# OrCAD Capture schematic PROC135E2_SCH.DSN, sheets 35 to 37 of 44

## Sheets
35 35. USB0 TYPE-C DRP & TEST LED: size C; title: USB0 TYPE-C DRP & USER TEST LED
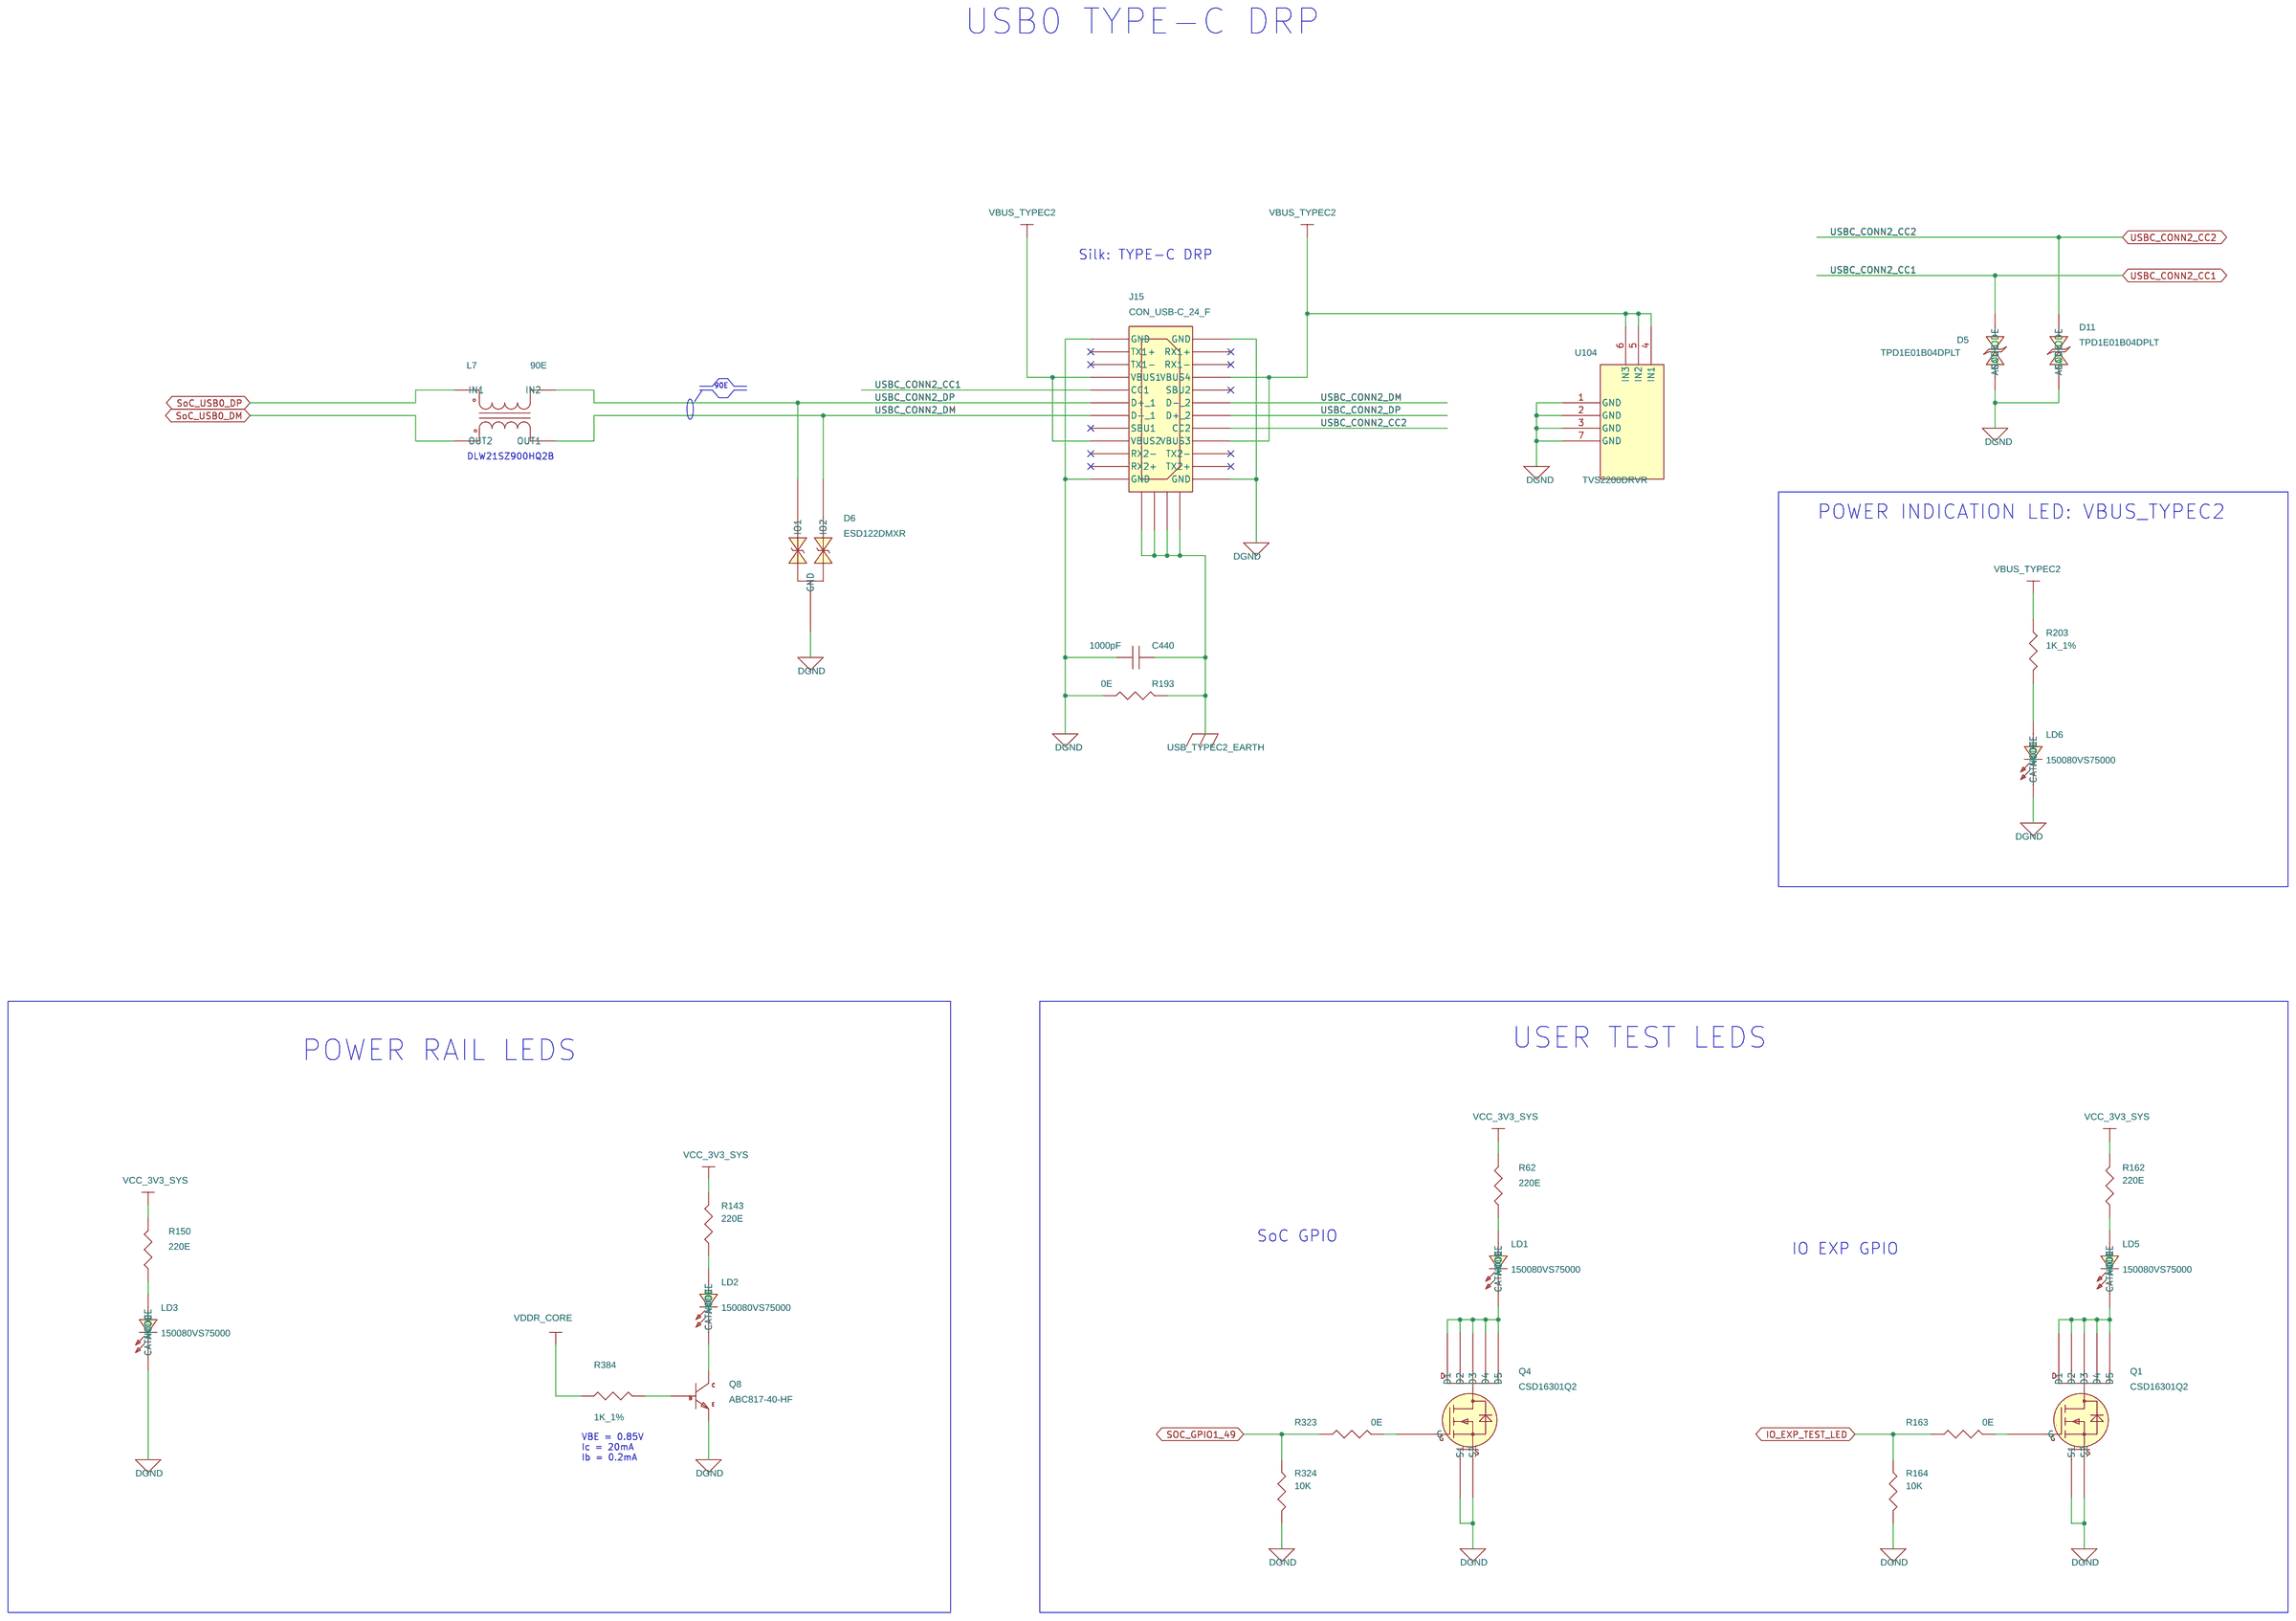
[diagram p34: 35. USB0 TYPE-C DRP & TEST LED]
36 36. SoC UART1 FET SWITCH & BUFF: size C; title: SoC UART1 FET SWITCH & BUFFER
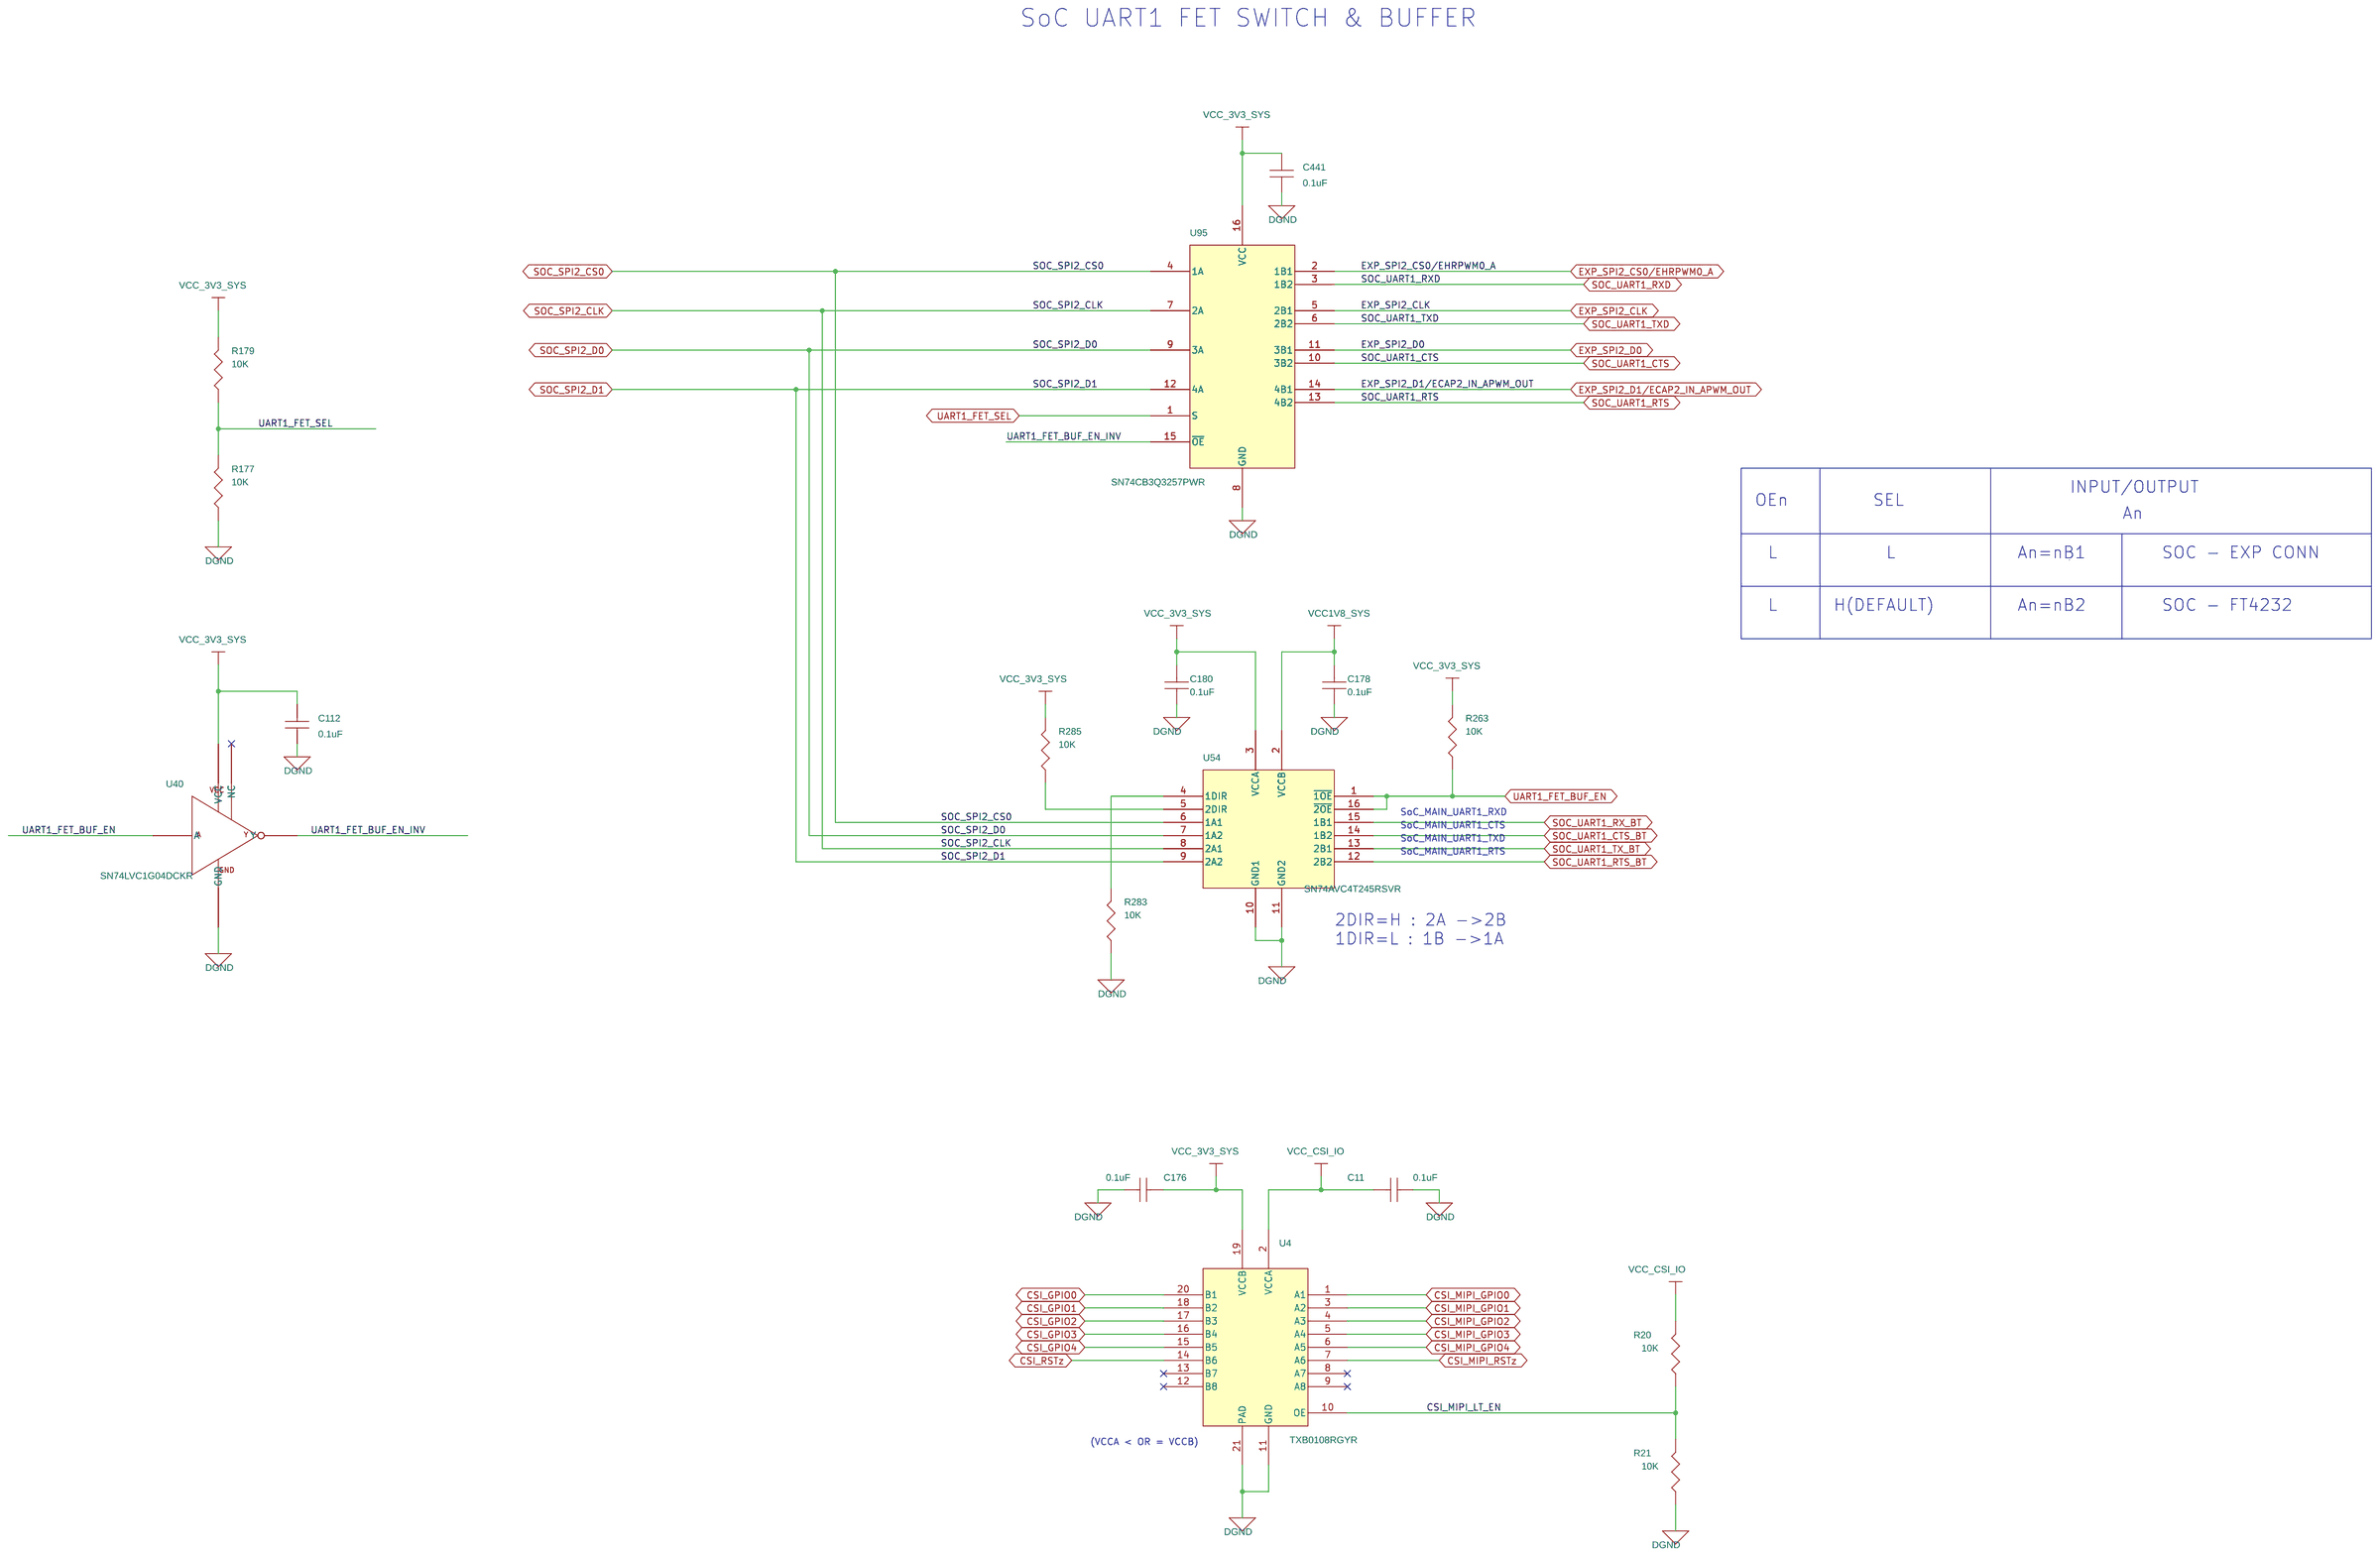
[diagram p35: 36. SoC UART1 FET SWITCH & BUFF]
37 37. CSI INTERFACE: size C; title: CSI INTERFACE
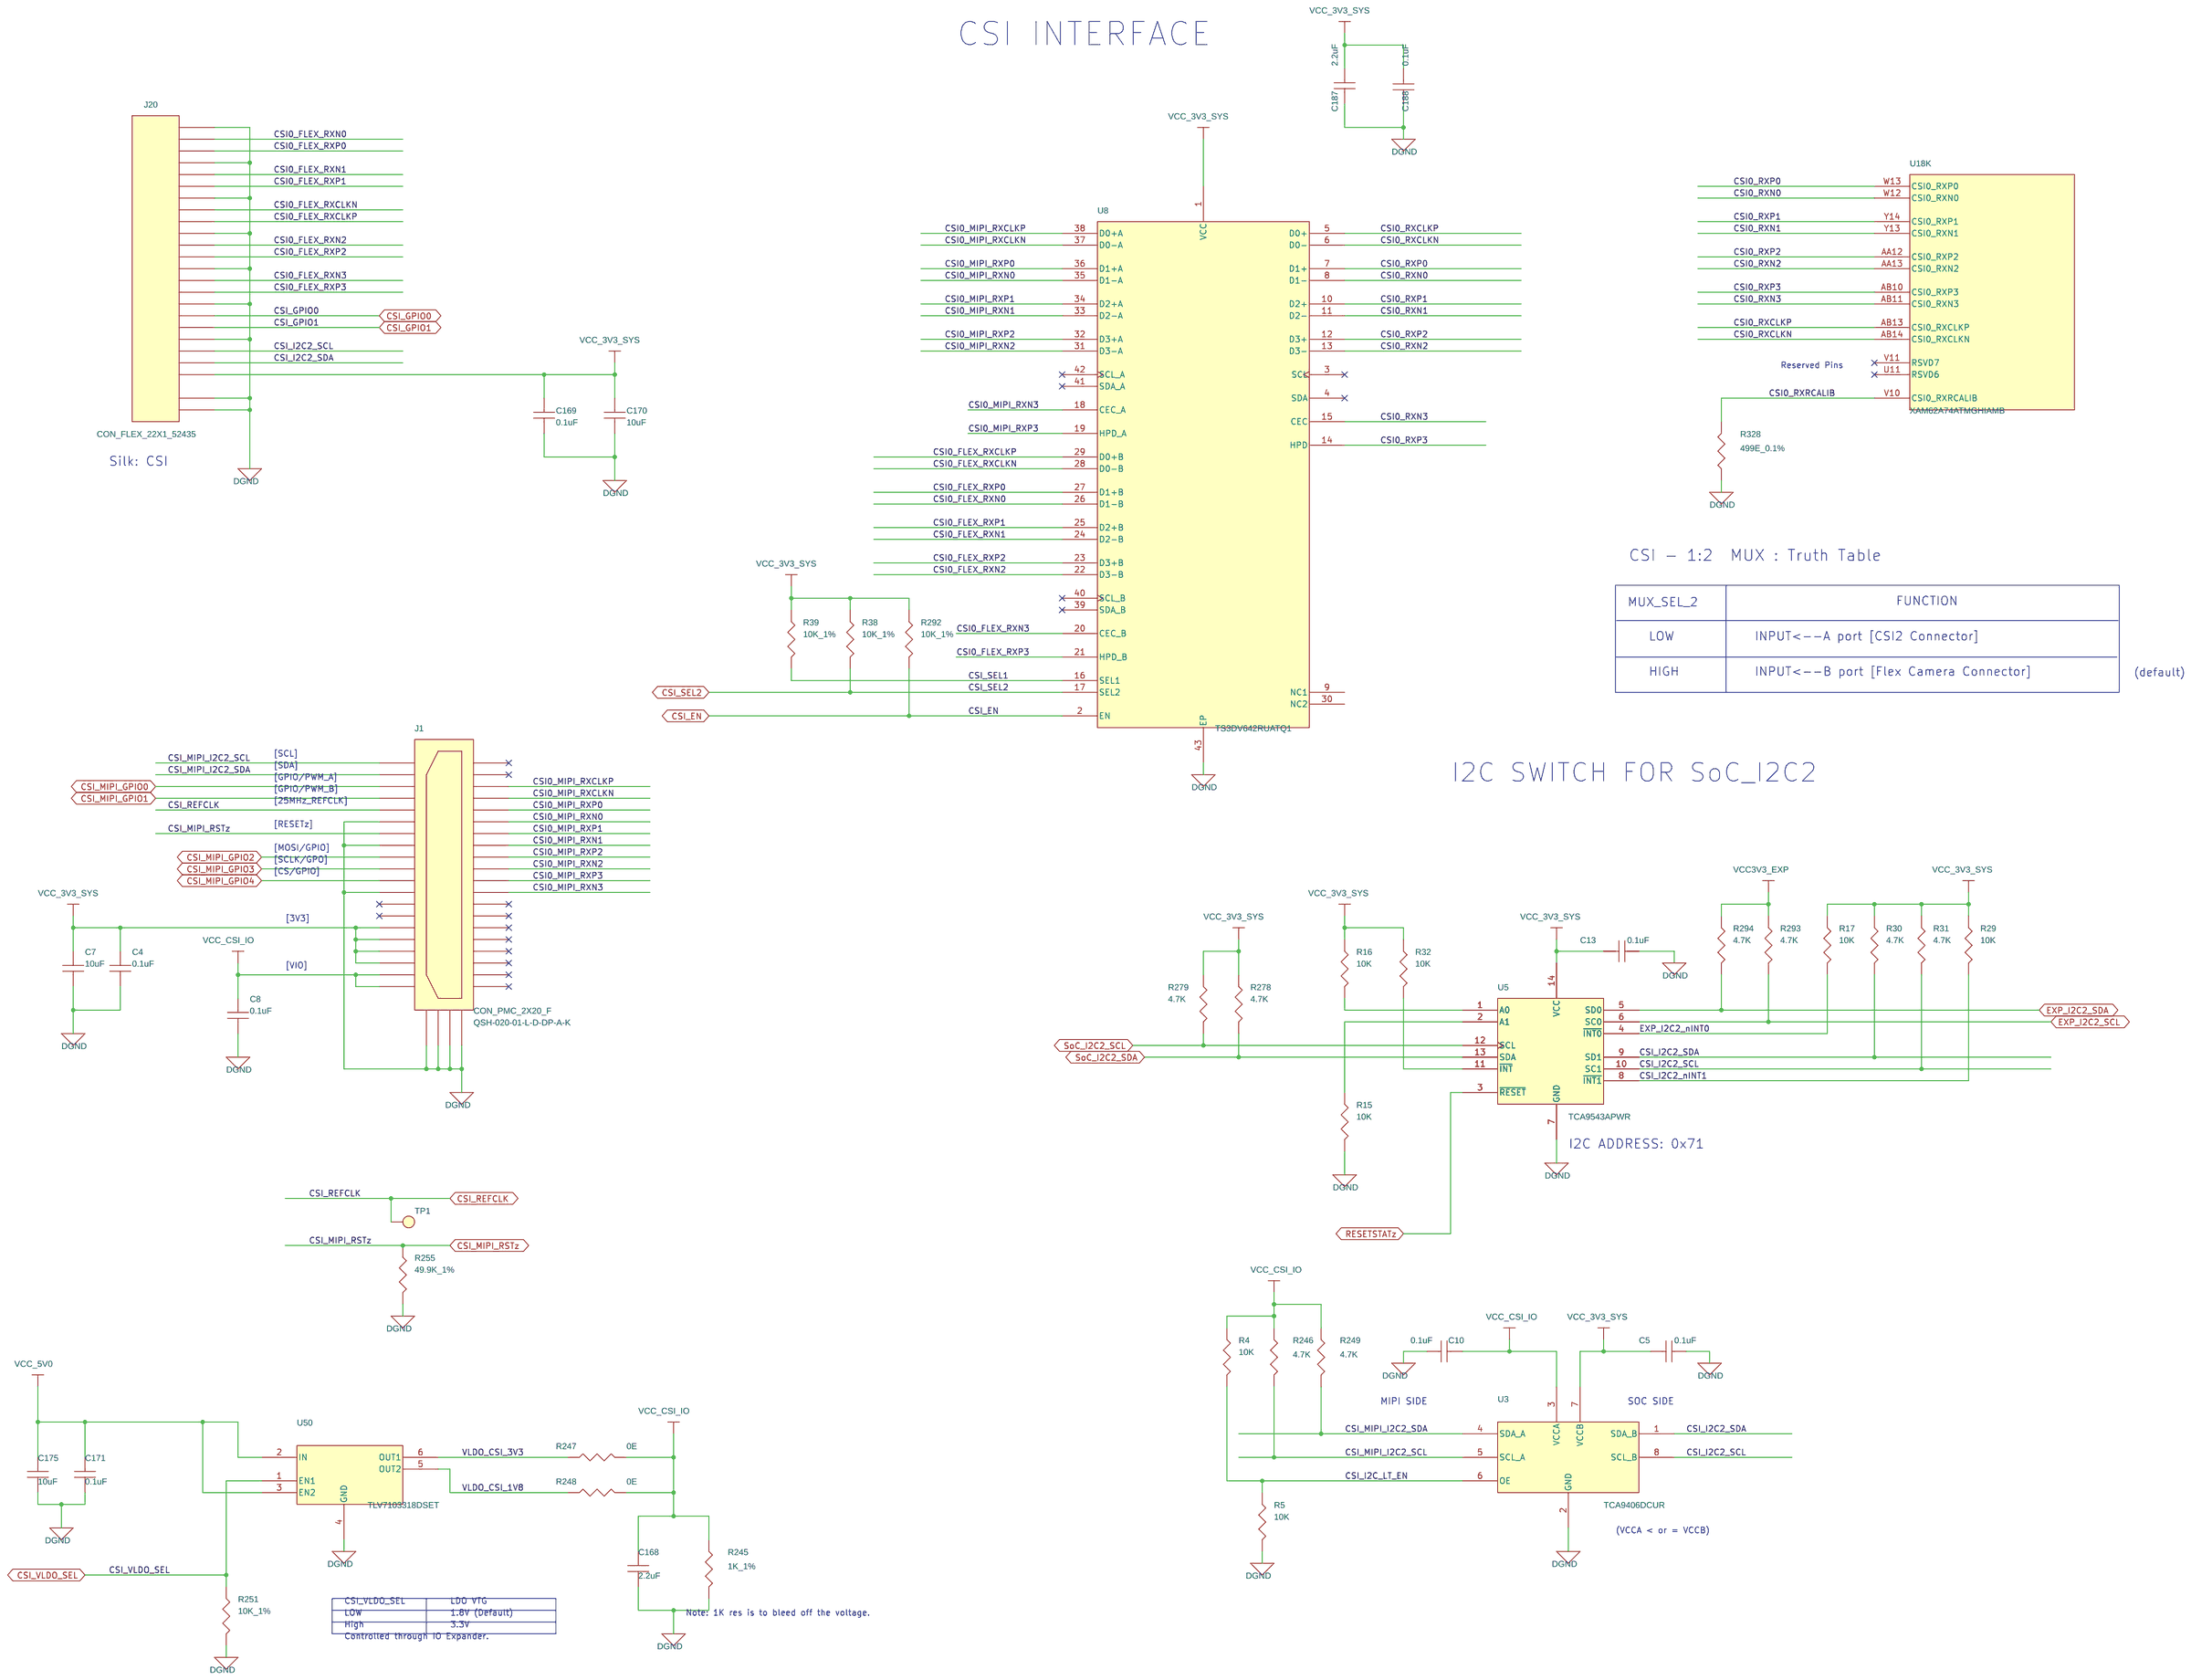
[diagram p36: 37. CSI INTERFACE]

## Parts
sheet 31. SOC WKUP & GPMC
U18  XAM62A74ATMGHIAMB  [FBGA484_31-49_710X710_2-7]  (sections A,B,C,D,E,F,G,H,I,J,K,L,M,N,O,P,Q)
sheet 35. USB0 TYPE-C DRP & TEST LED
C440  1000pF  [CAP1206_1-75]
D5  TPD1E01B04DPLT  [DIO_DFN0201_0-4]
D6  ESD122DMXR  [X2SON3_ESD122DMX_30X40_0-4]
D11  TPD1E01B04DPLT  [DIO_DFN0201_0-4]
J15  CON_USB-C_24_F  [CON_USBC24_2012670_S_R_S_3-9]
L7  90E  [IND4_DLW21H_90X60_SMD_1-4]
LD1  150080VS75000  [LED_150080VS75000_80X50_SMD_0-8]
LD2  150080VS75000  [LED_150080VS75000_80X50_SMD_0-8]
LD3  150080VS75000  [LED_150080VS75000_80X50_SMD_0-8]
LD5  150080VS75000  [LED_150080VS75000_80X50_SMD_0-8]
LD6  150080VS75000  [LED_150080VS75000_80X50_SMD_0-8]
Q1  CSD16301Q2  [WSON6_CSD13202Q2_80X80_0-8]
Q4  CSD16301Q2  [WSON6_CSD13202Q2_80X80_0-8]
Q8  ABC817-40-HF  [SOT23-123_1-2]
R62  220E  [RES0402_0-5]
R143  220E  [RES0402_0-5]
R150  220E  [RES0402_0-5]
R162  220E  [RES0402_0-5]
R163  0E  [RES0402_0-5]
R164  10K  [RES0201_0-5]
R193  0E  [RES0603_0-75]
R203  1K_1%  [RES0402_0-5]
R323  0E  [RES0402_0-5]
R324  10K  [RES0201_0-5]
R384  1K_1%  [RES0402_0-5]
U104  TVS2200DRVR  [SON6_25-59_85X85_0-8]
sheet 36. SoC UART1 FET SWITCH & BUFF
C11  0.1uF  [CAP0402_0-75]
C112  0.1uF  [CAP0201_0-5]
C176  0.1uF  [CAP0402_0-75]
C178  0.1uF  [CAP0201_0-5]
C180  0.1uF  [CAP0201_0-5]
C441  0.1uF  [CAP0402_0-75]
R20  10K  [RES0201_0-5]
R21  10K  [RES0201_0-5]
R177  10K  [RES0201_0-5]
R179  10K  [RES0201_0-5]
R263  10K  [RES0201_0-5]
R283  10K  [RES0201_0-5]
R285  10K  [RES0201_0-5]
U4  TXB0108RGYR  [QFN20_19-68_185X145_1]
U40  SN74LVC1G04DCKR  [SC70-5]
U54  SN74AVC4T245RSVR  [UQFN16_TMUX1574_70X100_0-6]
U95  SN74CB3Q3257PWR  [TSSOP16_25-59_205X180]
sheet 37. CSI INTERFACE
C4  0.1uF  [CAP0402_0-75]
C5  0.1uF  [CAP0402_0-75]
C7  10uF  [CAP0402_0-75]
C8  0.1uF  [CAP0402_0-75]
C10  0.1uF  [CAP0402_0-75]
C13  0.1uF  [CAP0402_0-75]
C168  2.2uF  [CAP0402_0-75]
C169  0.1uF  [CAP0402_0-75]
C170  10uF  [CAP0402_0-75]
C171  0.1uF  [CAP0402_0-75]
C175  10uF  [CAP0805_1-5]
C187  2.2uF  [CAP0402_0-75]
C188  0.1uF  [CAP0201_0-5]
J1  CON_PMC_2X20_F  [CON_PMC2X20_QSH-020-01-D-DP-A_S_S_S_3-4]
J20  CON_FLEX_22X1_52435  [CON_FLEX22X1_52435_S_R_S]
R4  10K  [RES0201_0-5]
R5  10K  [RES0201_0-5]
R15  10K  [RES0201_0-5]
R16  10K  [RES0201_0-5]
R17  10K  [RES0201_0-5]
R29  10K  [RES0201_0-5]
R30  4.7K  [RES0201_0-5]
R31  4.7K  [RES0201_0-5]
R32  10K  [RES0201_0-5]
R38  10K_1%  [RES0402_0-5]
R39  10K_1%  [RES0402_0-5]
R245  1K_1%  [RES0402_0-5]
R246  4.7K  [RES0201_0-5]
R247  0E  [RES0402_0-5]
R248  0E  [RES0402_0-5]
R249  4.7K  [RES0201_0-5]
R251  10K_1%  [RES0402_0-5]
R255  49.9K_1%  [RES0402_0-5]
R278  4.7K  [RES0201_0-5]
R279  4.7K  [RES0201_0-5]
R292  10K_1%  [RES0402_0-5]
R293  4.7K  [RES0201_0-5]
R294  4.7K  [RES0201_0-5]
R328  499E_0.1%  [RES0402_0-5]
TP1  TP20_SMD  [TP20_SMD]
U3  TCA9406DCUR  [VSSOP8_19-68_85X95]
U5  TCA9543APWR  [TSSOP14_25-59_205X180_1-2]
U8  TS3DV642RUATQ1  [TQFN42_19-68_140X360_0-8]
U50  TLV7103318DSET  [WSON6_19-68_60X60]

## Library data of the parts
U18 = AM62A-EVM_SOC_FCBGA484: IC AM62A SK EVM SoC MICROPROCESSOR FCBGA484; Chkd/date: PRAVEEN/190922; Crtd /date: PRAVEEN/190922; Custom_Duty: 15%; Customs_HS_Code: 85423100; Distributor_name: NA; Distributor_part_number: NA; Footprint Path: Y:\MIS_DATABASE\Library\ALTIUM_TOOL\PCB_FOOTPRINTS\Altium_Footprint_Lib.PcbLib; Height: 2.65MM; Library Ref: AM62A-EVM_SoC_FCBGA484; Mfr_name: TEXAS INSTRUMENTS; Mistral Part No: 141220090002; Package: FCBGA484; Part_type: ICS\DIGITAL\MICROPROCESSOR; Project: TI_AM62A_SK_EVM; RoHS: NA; Temperature: NA; Tolerance: NA; Voltage: NA; Wattage: NA; Weight: NA; Datasheet: Y:\MIS_DATABASE\DATASHEETS\ICS\DIGITAL\MICROCONTROLLER\AM62A_SK_EVM.PDF
C440 = CAP: CAP CERAMIC 1000pF 2KV 10% X7R 1206; Chkd/date: SHREESHAIL/291106; Crtd /date: MAZHAR/281106; Custom_Duty: 15%; Customs_HS_Code: 85322990; Distributor_name: DIGIKEY; Distributor_part_number: 478-2956-1-ND; Footprint Path: Y:\MIS_DATABASE\Library\ALTIUM_TOOL\PCB_FOOTPRINTS\Altium_Footprint_Lib.PcbLib; Height: 1.52MM; Library Path: Y:\MIS_DATABASE\Library\ALTIUM_TOOL\SCHEMATICS_PARTS\MS_DISCRETE_Library.schlib; Mfr_name: AVX CORPORATION; Mfr_part_number: 1206GC102KAT1A; Mistral Part No: 120015080006-R; Package: 1206; Part_type: CAPACITORS\CERAMIC; Project: ADR1B; RoHS: RoHS; Temperature: -55°C+125°C; Tolerance: 10%; Voltage: 2KV; Wattage: NA; Weight: 16.2mg; Datasheet: Y:\MIS_DATABASE\DATASHEETS\CAPACITORS\AVX_HV-MLC.PDF
D5 D11 = DIODE_TVS_DUAL: DIODE 1CH ESD PROTECTION FOR USB TYPE-C AND THUNDERBOLT3 X2SON2; Chkd/date: MANIRAJA/230920; Crtd /date: ALVY/230920; Custom_Duty: 15%; Customs_HS_Code: 85412900; Distributor_name: DIGIKEY; Distributor_part_number: 296-44484-1-ND; Footprint Path: Y:\MIS_DATABASE\Library\ALTIUM_TOOL\PCB_FOOTPRINTS\Altium_Footprint_Lib.PcbLib; Height: 0.32MM; Library Path: Y:\MIS_DATABASE\Library\ALTIUM_TOOL\SCHEMATICS_PARTS\MS_DISCRETE_Library.schlib; Mfr_name: TEXAS INSTRUMENTS; Mistral Part No: 130020090037-R; Package: X2SON2; Part_type: DIODE\TVS; Project: AM64X_SKEVM; RoHS: RoHS; Temperature: -40°C+125°C; Tolerance: NA; Voltage: NA; Wattage: NA; Weight: 0.2mg; Datasheet: Y:\MIS_DATABASE\DATASHEETS\DISCRETES\DIODES\TPD1E01B04.PDF
D6 = DIODE_ESD122DMXR: DIODE 2-CH ESD PROTECTION FOR USB TYPE-C AND HDMI 2.0 X2SON-3; Chkd/date: MANIRAJA/140817; Crtd /date: MANIRAJA/140817; Custom_Duty: 15%; Customs_HS_Code: 85412900; Distributor_name: DIGIKEY; Distributor_part_number: ESD122DMXR-ND; Height: 0.40MM; Mfr_name: TEXAS INSTRUMENTS; Mistral Part No: 130017080015-R; Package: X2SON-3; Part_type: DIODE\TVS; Project: TI_SVB_CONTROLLER CARD; RoHS: RoHS; Temperature: -40°C+125°C; Tolerance: NA; Voltage: NA; Wattage: NA; Weight: NA; Datasheet: Y:\MIS_DATABASE\DATASHEETS\DISCRETES\DIODES\ESD122XX.PDF
J15 = CON_USB-C_24_1240183621: CON USB-C TYPE 24POS FEMALE RT SMD; Chkd/date: MANIRAJA/050618; Crtd /date: ALVY/040618; Custom_Duty: 24%; Customs_HS_Code: 85369090; Distributor_name: DIGIKEY; Distributor_part_number: WM17992CT-ND; Footprint Path: Y:\MIS_DATABASE\Library\ALTIUM_TOOL\PCB_FOOTPRINTS\Altium_Footprint_Lib.PcbLib; Height: 3.86MM; Library Path: Y:\MIS_DATABASE\Library\ALTIUM_TOOL\SCHEMATICS_PARTS\MS_CONNECTOR_Library.schlib; Mfr_name: MOLEX; Mfr_part_number: 2012670005; Mistral Part No: 150018060002-R; Package: SMD; Part_type: CONNECTOR\USB; Project: TI_J7SVB_USB_ADD-ON-CARD; RoHS: RoHS; Temperature: -40°C+105°C; Tolerance: NA; Voltage: NA; Wattage: NA; Weight: 0.686g; Datasheet: Y:\MIS_DATABASE\DATASHEETS\CONNECTORS\2012670X.PDF
L7 = INDUCTOR_DLW31S: IND COMMON MODE CHOKE 90E 280mA SMD; Chkd/date: MANIRAJA/270619; Crtd /date: MANIRAJA/270619; Custom_Duty: 24%; Customs_HS_Code: 85437099; Distributor_name: NA; Distributor_part_number: NA; Footprint Path: Y:\MIS_DATABASE\Library\ALTIUM_TOOL\PCB_FOOTPRINTS\Altium_Footprint_Lib.PcbLib; Height: 1.40MM; Library Path: Y:\MIS_DATABASE\Library\ALTIUM_TOOL\SCHEMATICS_PARTS\MS_DISCRETE_Library.schlib; Mfr_name: MURATA; Mfr_part_number: DLW21SZ900HQ2B; Mistral Part No: 130019060035-R; Package: SMD; Part_type: INDUCTOR; Project: TI_J7ES_CP; RoHS: RoHS; Temperature: -40°C+105°C; Tolerance: NA; Voltage: NA; Wattage: NA; Weight: 11mg; Datasheet: Y:\MIS_DATABASE\DATASHEETS\DISCRETES\INDUCTORS\DLW21SZ900HQ2B.PDF
LD1-LD3 LD5 LD6 = DIODE_LED: DIODE LED BRIGHT GREEN SMD; Chkd/date: MANIRAJA/180820; Crtd /date: ALVY/180820; Custom_Duty: 24%; Customs_HS_Code: 85439000; Distributor_name: DIGIKEY; Distributor_part_number: 732-4986-1-ND; Footprint Path: Y:\MIS_DATABASE\Library\ALTIUM_TOOL\PCB_FOOTPRINTS\Altium_Footprint_Lib.PcbLib; Height: 0.80MM; Library Path: Y:\MIS_DATABASE\Library\ALTIUM_TOOL\SCHEMATICS_PARTS\MS_OPTO_Library.schlib; Mfr_name: WURTH ELECTRONICS; Mistral Part No: 130020080012-R; Package: SMD; Part_type: OPTO\LED; Project: AM64x_EVM_BRD; RoHS: RoHS; Temperature: -40°C+85°C; Tolerance: NA; Voltage: NA; Wattage: NA; Weight: 10mg; Datasheet: Y:\MIS_DATABASE\DATASHEETS\DISCRETES\LEDS\150080VS75000.PDF
Q1 Q4 = MOSFET_CSD17313Q2: IC MOSFET N-CHANNEL NEXFET 25V WSON6; Chkd/date: ALVY/071220; Crtd /date: MANIRAJA/071220; Custom_Duty: 15%; Customs_HS_Code: 85423100; Distributor_name: DIGIKEY; Distributor_part_number: 296-25260-1-ND; Footprint Path: Y:\MIS_DATABASE\Library\ALTIUM_TOOL\PCB_FOOTPRINTS\Altium_Footprint_Lib.PcbLib; Height: 0.80MM; Library Path: Y:\MIS_DATABASE\Library\ALTIUM_TOOL\SCHEMATICS_PARTS\MS_MOSFET_Library.schlib; Manufacturer: TEXAS INSTRUMENTS; Mfr_name: TEXAS INSTRUMENTS; Mistral Part No: 142020120008-R; Package: WSON6; Part_type: ICS\POWER\MOSFET; Project: TI_AM243x LP EVM; RoHS: RoHS; Temperature: -55°C+150°C; Tolerance: NA; Voltage: NA; Wattage: NA; Weight: 8.7mg; Datasheet: Y:\MIS_DATABASE\DATASHEETS\ICS\POWER\CSD16301Q2.PDF
Q8 = NPN_123_SOT23-3: TRANSISTOR 45V 500mA NPN GENERAL PURPOSE SOT23-3; Chkd/date: PRAVEEN/260822; Crtd /date: PRAVEEN/260822; Custom_Duty: 15%; Customs_HS_Code: 85423100; Distributor_name: MOUSER; Distributor_part_number: 750-ABC817-40-HF; Footprint Path: Y:\MIS_DATABASE\Library\ALTIUM_TOOL\PCB_FOOTPRINTS\Altium_Footprint_Lib.PcbLib; Height: 1.20MM; Library Path: Y:\MIS_DATABASE\Library\ALTIUM_TOOL\SCHEMATICS_PARTS\MS_MOSFET_Library.schlib; Mfr_name: COMCHIP; Mistral Part No: 142022080040-R; Package: TO-252-3; Part_type: TRANSISTOR\BJT; Project: MS_TI_TMDS64SKEVM; RoHS: RoHS; Temperature: -55°C+150°C; Tolerance: NA; Voltage: 45V; Wattage: NA; Weight: NA; Datasheet: Y:\MIS_DATABASE\DATASHEETS\DISCRETES\TRANSISTORS_FETS\ABC817-40-HF.PDF
R62 R143 R150 R162 = RESISTOR: RES 220E 1/10W 5% 0402; Chkd/date: VASANTHA/291216; Crtd /date: GEETHA/260406; Custom_Duty: 15%; Customs_HS_Code: 85332119; Distributor_name: DIGIKEY; Distributor_part_number: P220JCT-ND; Footprint Path: Y:\MIS_DATABASE\Library\ALTIUM_TOOL\PCB_FOOTPRINTS\Altium_Footprint_Lib.PcbLib; Height: 0.40MM; Library Path: Y:\MIS_DATABASE\Library\ALTIUM_TOOL\SCHEMATICS_PARTS\MS_DISCRETE_Library.schlib; Mfr_name: PANASONIC-ECG; Mfr_part_number: ERJ-2GEJ221X; Mistral Part No: 110009030506-R; Package: 0402; Part_type: RESISTORS\FIXED; Project: RED EYE; RoHS: RoHS; Temperature: -55°C+155°C; Tolerance: 5%; Voltage: NA; Wattage: 1/10W; Weight: 0.8mg; Datasheet: Y:\MIS_DATABASE\DATASHEETS\RESISTORS\PAN-ERJSER_NOV17.PDF
R163 R323 = RESISTOR: RES 0E 1/16W JUMPER 0402; Chkd/date: VASANTHA/201216; Crtd /date: MUDDU/190810; Custom_Duty: 15%; Customs_HS_Code: 85332119; Distributor_name: DIGIKEY; Distributor_part_number: 541-0.0JCT-ND; Footprint Path: Y:\MIS_DATABASE\Library\ALTIUM_TOOL\PCB_FOOTPRINTS\Altium_Footprint_Lib.PcbLib; Height: 0.40MM; Library Path: Y:\MIS_DATABASE\Library\ALTIUM_TOOL\SCHEMATICS_PARTS\MS_DISCRETE_Library.schlib; Mfr_name: VISHAY; Mfr_part_number: CRCW04020000Z0ED; Mistral Part No: 110010080019-R; Package: 0402; Part_type: RESISTORS\FIXED; Project: PB_BUGBASE; RoHS: RoHS; Temperature: -55°C+155°C; Tolerance: NA; Voltage: NA; Wattage: 1/16W; Weight: 0.65mg; Datasheet: Y:\MIS_DATABASE\DATASHEETS\RESISTORS\CRCW0603.PDF
R4 R5 R15-R17 R20 R21 R29 R32 R164 R177 R179 R263 R283 R285 R324 = RESISTOR: RES 10K 1/20W 5% 0201; Chkd/date: MANIRAJA/050517; Crtd /date: MANIRAJA/050517; Custom_Duty: 15%; Customs_HS_Code: 85332119; Distributor_name: DIGIKEY; Distributor_part_number: 311-10KNCT-ND; Footprint Path: Y:\MIS_DATABASE\Library\ALTIUM_TOOL\PCB_FOOTPRINTS\Altium_Footprint_Lib.PcbLib; Height: 0.26MM; Library Path: Y:\MIS_DATABASE\Library\ALTIUM_TOOL\SCHEMATICS_PARTS\MS_DISCRETE_Library.schlib; Mfr_name: YAGEO AMERICA; Mfr_part_number: RC0201JR-0710KL; Mistral Part No: 110010070051-R; Package: 0201; Part_type: RESISTORS\FIXED; Project: GOLDEN-I LITE; RoHS: RoHS; Temperature: -55°C+125°C; Tolerance: 5%; Voltage: NA; Wattage: 1/20W; Weight: 0.17mg; Datasheet: Y:\MIS_DATABASE\DATASHEETS\RESISTORS\RCXXXXL-SER_MAR18.PDF
R193 = RESISTOR: RES 0E 1/10W 5% 0603; Chkd/date: MANIRAJA/051217; Crtd /date: BAVISH/180211; Custom_Duty: 15%; Customs_HS_Code: 85332119; Distributor_name: DIGIKEY; Distributor_part_number: 311-0.0GRCT-ND; Footprint Path: Y:\MIS_DATABASE\Library\ALTIUM_TOOL\PCB_FOOTPRINTS\Altium_Footprint_Lib.PcbLib; Height: 0.55MM; Library Path: Y:\MIS_DATABASE\Library\ALTIUM_TOOL\SCHEMATICS_PARTS\MS_DISCRETE_Library.schlib; Manufacturer: YAGEO AMERICA; Mfr_name: PANASONIC-ECG; Mfr_part_number: RC0603JR-070RL; Mistral Part No: 110011020013-R; Package: 0603; Part_type: RESISTORS\FIXED; Project: KENNEL; RoHS: RoHS; Temperature: -55°C+155°C; Tolerance: 5%; Voltage: NA; Wattage: 1/10W; Weight: 2mg; Datasheet: Y:\MIS_DATABASE\DATASHEETS\RESISTORS\RCXXXXL-SER_MAR18.PDF
R203 R245 R384 = RESISTOR: RES 1K 1/10W 1% 0402; Chkd/date: VASANTHA/281216; Crtd /date: MAZHAR/150506; Custom_Duty: 15%; Customs_HS_Code: 85332119; Distributor_name: DIGIKEY; Distributor_part_number: P1.00KLCT-ND; Footprint Path: Y:\MIS_DATABASE\Library\ALTIUM_TOOL\PCB_FOOTPRINTS\Altium_Footprint_Lib.PcbLib; Height: 0.40MM; Library Path: Y:\MIS_DATABASE\Library\ALTIUM_TOOL\SCHEMATICS_PARTS\MS_DISCRETE_Library.schlib; Mfr_name: PANASONIC-ECG; Mfr_part_number: ERJ-2RKF1001X; Mistral Part No: 110009030411-R; Package: 0402; Part_type: RESISTORS\FIXED; Project: VOCERA; RoHS: RoHS; Temperature: -55°C+155°C; Tolerance: 1%; Voltage: NA; Wattage: 1/10W; Weight: 0.8mg; Datasheet: Y:\MIS_DATABASE\DATASHEETS\RESISTORS\PAN-ERJSER_NOV17.PDF
U104 = TVS2200_WSON6: IC 22V FLAT-CLAMP SURGE PROTECTION DEVICE WSON6; Chkd/date: MANIRAJA/011021; Crtd /date: ALVY/011021; Custom_Duty: 15%; Customs_HS_Code: 85423100; Distributor_name: DIGIKEY; Distributor_part_number: 296-52187-1-ND; Footprint Path: Y:\MIS_DATABASE\Library\ALTIUM_TOOL\PCB_FOOTPRINTS\Altium_Footprint_Lib.PcbLib; Height: 0.80MM; Library Path: Y:\MIS_DATABASE\Library\ALTIUM_TOOL\SCHEMATICS_PARTS\MS_MISCPOWER_Library.schlib; Mfr_name: TEXAS INSTRUMENTS; Mistral Part No: 142021100001-R; Package: WSON6; Part_type: ICS\POWER; Project: TI_AM62x SKEVM_BRD; RoHS: RoHS; Temperature: -40°C+125°C; Tolerance: NA; Voltage: NA; Wattage: NA; Weight: 12mg; Datasheet: Y:\MIS_DATABASE\DATASHEETS\ICS\POWER\TVS2200.PDF
C4 C5 C8 C10 C11 C13 C169 C171 C176 C441 = CAP: CAP CERAMIC 0.1uF 50V 10% X7R 0402; Alt_Mfr_name: YAGEO AMERICA; Alt_Mfr_part_number: CC0402KRX5R8BB104; Chkd/date: MANIRAJA/261020; Crtd /date: ALVY/211020; Custom_Duty: 15%; Customs_HS_Code: 85322990; Distributor_name: DIGIKEY; Distributor_part_number: 490-10700-1-ND; Footprint Path: Y:\MIS_DATABASE\Library\ALTIUM_TOOL\PCB_FOOTPRINTS\Altium_Footprint_Lib.PcbLib; Height: 0.55MM; Library Path: Y:\MIS_DATABASE\Library\ALTIUM_TOOL\SCHEMATICS_PARTS\MS_DISCRETE_Library.schlib; Mfr_name: MURATA; Mfr_part_number: GRM155R71H104KE14D; Mistral Part No: 120011100014-R; Package: 0402; Part_type: CAPACITORS\CERAMIC; Project: J7_CP; RoHS: RoHS; Temperature: -55°C+125°C; Tolerance: 10%; Voltage: 50V; Wattage: NA; Weight: 3.1mg; Datasheet: Y:\MIS_DATABASE\DATASHEETS\CAPACITORS\GRM155R71H104KE14.PDF
C112 C178 C180 C188 = CAP: CAP CERAMIC 0.1uF 16V 10% X5R 0201; Alt_Mfr_name: YAGEO AMERICA; Alt_Mfr_part_number: CC0402KRX5R8BB104; Chkd/date: MANIRAJA/230118; Crtd /date: MANIRAJA/230118; Custom_Duty: 15%; Customs_HS_Code: 85322990; Distributor_name: DIGIKEY; Distributor_part_number: 490-14305-1-ND; Footprint Path: Y:\MIS_DATABASE\Library\ALTIUM_TOOL\PCB_FOOTPRINTS\Altium_Footprint_Lib.PcbLib; Height: 0.33MM; Library Path: Y:\MIS_DATABASE\Library\ALTIUM_TOOL\SCHEMATICS_PARTS\MS_DISCRETE_Library.schlib; Mfr_name: MURATA; Mfr_part_number: GRM033R61C104KE14D; Mistral Part No: 120009030072-R; Package: 0201; Part_type: CAPACITORS\CERAMIC; Project: TI_MAXIE_CPB; RoHS: RoHS; Temperature: -55°C+85°C; Tolerance: 10%; Voltage: 16V; Wattage: NA; Weight: 0.33mg; Datasheet: Y:\MIS_DATABASE\DATASHEETS\CAPACITORS\GRM033R61C104KE14.PDF
U4 = TXB0108RGYR_VQFN20: IC 8-BIT TRANSLATOR 15KV ESD VQFN20; Chkd/date: VASANTHA/221216; Crtd /date: MUDDU/190510; Custom_Duty: 15%; Customs_HS_Code: 85423100; Distributor_name: DIGIKEY; Distributor_part_number: 296-21528-1-ND; Height: 1.00MM; Mfr_name: TEXAS INSTRUMENTS; Mistral Part No: 141010050005-R; Package: VQFN20; Part_type: ICS\INTERFACE; Project: SHIVA; RoHS: Sb/ Br FREE; Temperature: -40°C+85°C; Tolerance: NA; Voltage: NA; Wattage: NA; Weight: 43mg; Datasheet: Y:\MIS_DATABASE\DATASHEETS\ICS\INTERFACE\TXB0108RGYR.PDF
U40 = SN74LVC1G04DCKR_SC70-5: IC SINGLE INVERTER GATE SC70-5; Chkd/date: SUHAS/221010; Crtd /date: USMAN/150709; Custom_Duty: 15%; Customs_HS_Code: 85423100; Distributor_name: DIGIKEY; Distributor_part_number: 296-11600-1-ND; Height: 1.10MM; Mfr_name: TEXAS INSTRUMENTS; Mistral Part No: 141009070007-R; Part_type: ICS\DIGITAL\GATES; Project: BUG_BASE-II; RoHS: Sb/ Br FREE; Temperature: -40°C+85°C; Datasheet: Y:\MIS_DATABASE\DATASHEETS\ICS\DIGITAL\GATES\SN74LVC1G04-1.PDF
U54 = SN74AVC4T245RSV_UQFN16: IC 2-BIT BUS TRANSCEIVER WITH CONFIGURABLE VOLTAGE TRANSLATION AND 3 STATE O/P UQFN16; Chkd/date: MANIRAJA/040520; Crtd /date: BAVISH/190411; Custom_Duty: 15%; Customs_HS_Code: 85423100; Distributor_name: DIGIKEY; Distributor_part_number: 296-24366-1-ND; Footprint Path: Y:\MIS_DATABASE\Library\ALTIUM_TOOL\PCB_FOOTPRINTS\Altium_Footprint_Lib.PcbLib; Height: 0.55MM; Library Path: Y:\MIS_DATABASE\Library\ALTIUM_TOOL\SCHEMATICS_PARTS\MS_BUSDRIVERTRANSCEIVER_Library.schlib; Mfr_name: TEXAS INSTRUMENTS; Mistral Part No: 141011040011-R; Package: UQFN16; Part_type: ICS\DIGITAL\BUSTRANSCEIVER; Project: HMC; RoHS: RoHS; Temperature: -40°C+85°C; Tolerance: NA; Voltage: NA; Wattage: NA; Weight: 41mg; Datasheet: Y:\MIS_DATABASE\DATASHEETS\ICS\DIGITAL\BUSTRANSCEIVER\SN74AVC4T245-SER.PDF
U95 = SN74CB3Q3257PWR_TSSOP16: IC 4BIT 1-OF-2 FET MULTIPLEXER/DEMULTIPLEXER TSSOP16; Chkd/date: SUHAS/251010; Crtd /date: USMAN/060109; Custom_Duty: 15%; Customs_HS_Code: 85423100; Distributor_name: DIGIKEY; Distributor_part_number: 296-19138-1-ND; Height: 1.20MM; Mfr_name: TEXAS INSTRUMENTS; Mistral Part No: 141009030117-R; Package: TSSOP16; Part_type: ICS\DIGITAL\COMBINATIONAL; Project: OMAP_EVM; RoHS: Sb/ Br FREE; Temperature: -40°C+85°C; Datasheet: Y:\MIS_DATABASE\DATASHEETS\ICS\DIGITAL\COMBINATIONAL\SN74CB3Q3257.PDF
C7 C170 = CAP: CAP CERAMIC 10uF 10V 20% X5R 0402; Chkd/date: MANIRAJA/300520; Crtd /date: ALVY/260520; Custom_Duty: 15%; Customs_HS_Code: 85322990; Distributor_name: DIGIKEY; Distributor_part_number: 490-GRM155R61A106ME11DTR-ND; Footprint Path: Y:\MIS_DATABASE\Library\ALTIUM_TOOL\PCB_FOOTPRINTS\Altium_Footprint_Lib.PcbLib; Height: 0.55MM; Library Path: Y:\MIS_DATABASE\Library\ALTIUM_TOOL\SCHEMATICS_PARTS\MS_DISCRETE_Library.schlib; Mfr_name: MURATA; Mfr_part_number: GRM155R61A106ME11D; Mistral Part No: 120013110019-R; Package: 0402; Part_type: CAPACITORS\CERAMIC; Project: QCS610_NANOSOM; RoHS: RoHS; Temperature: -55°C+85°C; Tolerance: 20%; Voltage: 10V; Wattage: NA; Weight: 3.1mg; Datasheet: Y:\MIS_DATABASE\DATASHEETS\CAPACITORS\MURATA-GXX-SER_NOV17.PDF
C168 = CAP: CAP CERAMIC 2.2uF 25V 10% X5R 0402; Chkd/date: ALVY/010721; Crtd /date: MANIRAJA/010721; Custom_Duty: 15%; Customs_HS_Code: 85322990; Distributor_name: DIGIKEY; Distributor_part_number: 490-12703-1-ND; Footprint Path: Y:\MIS_DATABASE\Library\ALTIUM_TOOL\PCB_FOOTPRINTS\Altium_Footprint_Lib.PcbLib; Height: 0.70MM; Library Path: Y:\MIS_DATABASE\Library\ALTIUM_TOOL\SCHEMATICS_PARTS\MS_DISCRETE_Library.schlib; Manufacturer: MURATA; Mfr_name: MURATA; Mfr_part_number: GRM155R61E225KE11D; Mistral Part No: 120015120001-R; Package: 0402; Part_type: CAPACITORS\CERAMIC; Project: TI_AM263X_CC; RoHS: RoHS; Temperature: -55°C+85°C; Tolerance: 10%; Voltage: 25V; Wattage: NA; Weight: 1.5mg; Datasheet: Y:\MIS_DATABASE\DATASHEETS\CAPACITORS\GRM155R61E225KE11.PDF
C175 = CAP: CAP CERAMIC 10uF 50V 10% X5R 0805; Chkd/date: MANIRAJA/010321; Crtd /date: ALVY/010321; Custom_Duty: 15%; Customs_HS_Code: 85322990; Distributor_name: DIGIKEY; Distributor_part_number: 490-18663-1-ND; Footprint Path: Y:\MIS_DATABASE\Library\ALTIUM_TOOL\PCB_FOOTPRINTS\Altium_Footprint_Lib.PcbLib; Height: 1.45MM; Library Path: Y:\MIS_DATABASE\Library\ALTIUM_TOOL\SCHEMATICS_PARTS\MS_DISCRETE_Library.schlib; Manufacturer: MURATA; Mfr_name: MURATA; Mfr_part_number: GRM21BR61H106KE43L; Mistral Part No: 120021030002-R; Package: 0805; Part_type: CAPACITORS\CERAMIC; Project: J7ES_SK_BRD; RoHS: RoHS; Temperature: -55°C+85°C; Tolerance: 10%; Voltage: 50V; Wattage: NA; Weight: 6.4mg; Datasheet: Y:\MIS_DATABASE\DATASHEETS\CAPACITORS\GRM21BR61H106KE43.PDF
C187 = CAP: CAP CERAMIC 2.2uF 25V 10% X5R 0402; Chkd/date: ALVY/010721; Crtd /date: MANIRAJA/010721; Custom_Duty: 15%; Customs_HS_Code: 85322990; Distributor_name: DIGIKEY; Distributor_part_number: 490-12703-1-ND; Footprint Path: Y:\MIS_DATABASE\Library\ALTIUM_TOOL\PCB_FOOTPRINTS\Altium_Footprint_Lib.PcbLib; Height: 0.70MM; Library Path: Y:\MIS_DATABASE\Library\ALTIUM_TOOL\SCHEMATICS_PARTS\MS_DISCRETE_Library.schlib; Mfr_name: MURATA; Mfr_part_number: GRM155R61E225KE11D; Mistral Part No: 120015120001-R; Package: 0402; Part_type: CAPACITORS\CERAMIC; Project: TI_AM263X_CC; RoHS: RoHS; Temperature: -55°C+85°C; Tolerance: 10%; Voltage: 25V; Wattage: NA; Weight: 1.5mg; Datasheet: Y:\MIS_DATABASE\DATASHEETS\CAPACITORS\GRM155R61E225KE11.PDF
J1 = CON_PMC_20X2_F_DP_TI: CON PMC 2X20 0.50MM PITCH FEMALE ST SMD; Chkd/date: MANIRAJA/251018; Crtd /date: ALVY/251018; Custom_Duty: 24%; Customs_HS_Code: 85369090; Distributor_name: DIGIKEY; Distributor_part_number: SAM10648-ND; Footprint Path: Y:\MIS_DATABASE\Library\ALTIUM_TOOL\PCB_FOOTPRINTS\Altium_Footprint_Lib.PcbLib; Height: 3.33MM; Library Path: Y:\MIS_DATABASE\Library\ALTIUM_TOOL\SCHEMATICS_PARTS\MS_CONNECTOR_Library.schlib; Library Ref: CON_PMC_20X2_F_DP; Mfr_name: SAMTEC; Mfr_part_number: QSH-020-01-L-D-DP-A-K; Mistral Part No: 150018100049-R; Package: SMD; Part_type: CONNECTOR\PMC; Project: TI_J7ES_EVM_CP; RoHS: RoHS; Temperature: -55°C+125°C; Tolerance: NA; Voltage: NA; Wattage: NA; Weight: NA; Datasheet: Y:\MIS_DATABASE\DATASHEETS\CONNECTORS\QSH-SERIES.PDF
J20 = CON_22X1_2SH: CON FPC 22X1 0.50MM PITCH TPM RT SMD; Chkd/date: PRAVEEN/090822; Crtd /date: PRAVEEN/090822; Custom_Duty: 24%; Customs_HS_Code: 85369090; Distributor_name: DIGIKEY; Distributor_part_number: WM6753CT-ND; Height: 2.00MM; Mfr_name: MOLEX; Mfr_part_number: 52435-2271; Mistral Part No: 150022080019-R; Package: SMD; Part_type: CONNECTOR\FPC; Project: JHAHP_SVB; RoHS: RoHS; Temperature: -20°C to +85°C; Tolerance: NA; Voltage: NA; Wattage: NA; Datasheet: Y:\MIS_DATABASE\DATASHEETS\CONNECTORS\52435.PDF
R30 R31 R246 R249 R278 R279 R293 R294 = RESISTOR: RES 4.7K 1/20W 5% 0201; Chkd/date: MANIRAJA/200921; Crtd /date: ALVY/200921; Custom_Duty: 15%; Customs_HS_Code: 85332119; Distributor_name: DIGIKEY; Distributor_part_number: 311-4.7KNCT-ND; Footprint Path: Y:\MIS_DATABASE\Library\ALTIUM_TOOL\PCB_FOOTPRINTS\Altium_Footprint_Lib.PcbLib; Height: 0.26MM; Library Path: Y:\MIS_DATABASE\Library\ALTIUM_TOOL\SCHEMATICS_PARTS\MS_DISCRETE_Library.schlib; Mfr_name: YAGEO AMERICA; Mfr_part_number: RC0201JR-074K7L; Mistral Part No: 110021090007-R; Package: 0201; Part_type: RESISTORS\FIXED; Project: TI_AM62x SKEVM_BRD; RoHS: RoHS; Temperature: -55°C+125°C; Tolerance: 5%; Voltage: NA; Wattage: 1/20W; Weight: 0.17mg; Datasheet: Y:\MIS_DATABASE\DATASHEETS\RESISTORS\RCXXXXL-SER_MAR18.PDF
R38 R39 R251 R292 = RESISTOR: RES 10K 1/10W 1% AUTO 0402; Chkd/date: MANIRAJA/191020; Crtd /date: ALVY/191020; Custom_Duty: 15%; Customs_HS_Code: 85332119; Distributor_name: DIGIKEY; Distributor_part_number: MCS0402-10.0K-MFCT-ND; Footprint Path: Y:\MIS_DATABASE\Library\ALTIUM_TOOL\PCB_FOOTPRINTS\Altium_Footprint_Lib.PcbLib; Height: 0.37MM; Library Path: Y:\MIS_DATABASE\Library\ALTIUM_TOOL\SCHEMATICS_PARTS\MS_DISCRETE_Library.schlib; Manufacturer: VISHAY; Mfr_name: VISHAY; Mfr_part_number: MCS0402MC1002FE000; Mistral Part No: 110020100039-R; Package: 0402; Part_type: RESISTORS\FIXED; Project: MCX_80MHz_ADC_DRIVER; RoHS: RoHS; Temperature: -55°C+175°C; Tolerance: 1%; Voltage: NA; Wattage: 1/10W; Weight: 0.65mg; Datasheet: Y:\MIS_DATABASE\DATASHEETS\RESISTORS\MCTXXXXM-SER.PDF
R247 R248 = RESISTOR: RES 0E 1/16W JUMPER 0402; Chkd/date: VASANTHA/201216; Crtd /date: MUDDU/190810; Custom_Duty: 15%; Customs_HS_Code: 85332119; Distributor_name: DIGIKEY; Distributor_part_number: 541-0.0JCT-ND; Footprint Path: Y:\MIS_DATABASE\Library\ALTIUM_TOOL\PCB_FOOTPRINTS\Altium_Footprint_Lib.PcbLib; Height: 0.40MM; Library Path: Y:\MIS_DATABASE\Library\ALTIUM_TOOL\SCHEMATICS_PARTS\MS_DISCRETE_Library.schlib; Manufacturer: VISHAY; Mfr_name: VISHAY; Mfr_part_number: CRCW04020000Z0ED; Mistral Part No: 110010080019-R; Package: 0402; Part_type: RESISTORS\FIXED; Project: PB_BUGBASE; RoHS: RoHS; Temperature: -55°C+155°C; Tolerance: NA; Voltage: NA; Wattage: 1/16W; Weight: 0.65mg; Datasheet: Y:\MIS_DATABASE\DATASHEETS\RESISTORS\CRCW0603.PDF
R255 = RESISTOR: RES 49.9K 1/10W 1% 0402; Chkd/date: MANIRAJA/130617; Crtd /date: BAVISH/020611; Custom_Duty: 15%; Customs_HS_Code: 85332119; Distributor_name: DIGIKEY; Distributor_part_number: P49.9KLCT-ND; Footprint Path: Y:\MIS_DATABASE\Library\ALTIUM_TOOL\PCB_FOOTPRINTS\Altium_Footprint_Lib.PcbLib; Height: 0.40MM; Library Path: Y:\MIS_DATABASE\Library\ALTIUM_TOOL\SCHEMATICS_PARTS\MS_DISCRETE_Library.schlib; Manufacturer: VISHAY; Mfr_name: PANASONIC-ECG; Mfr_part_number: ERJ-2RKF4992X; Mistral Part No: 110011060018-R; Package: 0402; Part_type: RESISTORS\FIXED; Project: AM4515_EVM_LCD; RoHS: RoHS; Temperature: -55°C+155°C; Tolerance: 1%; Voltage: NA; Wattage: 1/10W; Weight: 0.8mg; Datasheet: Y:\MIS_DATABASE\DATASHEETS\RESISTORS\PAN-ERJSER_NOV17.PDF
R328 = RESISTOR: RES 499E 1/16W 0.1% 0402; Chkd/date: ALVY/200921; Crtd /date: MANIRAJA/200921; Custom_Duty: 15%; Customs_HS_Code: 85332119; Distributor_name: DIGIKEY; Distributor_part_number: YAG1440CT-ND; Footprint Path: Y:\MIS_DATABASE\Library\ALTIUM_TOOL\PCB_FOOTPRINTS\Altium_Footprint_Lib.PcbLib; Height: 0.35MM; Library Path: Y:\MIS_DATABASE\Library\ALTIUM_TOOL\SCHEMATICS_PARTS\MS_DISCRETE_Library.schlib; Mfr_name: YAGEO AMERICA; Mfr_part_number: RT0402BRD07499RL; Mistral Part No: 110021020006-R; Package: 0402; Part_type: RESISTORS\FIXED; Project: TI_AM62x SKEVM_BRD; RoHS: RoHS; Temperature: -55°C+155°C; Tolerance: 0.1%; Voltage: NA; Wattage: 1/16W; Weight: 0.65mg; Datasheet: Y:\MIS_DATABASE\DATASHEETS\RESISTORS\YAGEO_RT-SERIES.PDF
TP1 = TESTPOINT: TESTPOINT CIR 20 SMD; Chkd/date: SHREESHAIL/171006; Crtd /date: MAZHAR/171006; Custom_Duty: NA; Customs_HS_Code: NA; Distributor_name: NA; Distributor_part_number: NA; Footprint Path: Y:\MIS_DATABASE\Library\ALTIUM_TOOL\PCB_FOOTPRINTS\Altium_Footprint_Lib.PcbLib; Height: NA; Library Path: Y:\MIS_DATABASE\Library\ALTIUM_TOOL\SCHEMATICS_PARTS\MS_DISCRETE_Library.schlib; MECHANICAL 3D STEP FILE: NA; Mfr_name: LOCAL; Mistral Part No: NA; Package: SMD; Project: BT MODULE_CSRBC04; RoHS: NA; Temperature: NA; Tolerance: NA; Voltage: NA; Wattage: NA; Weight: NA; Datasheet: NA
U3 = TCA9406DCUR_VSSOP8: IC VOLTAGE-LEVEL TRANSLATOR 2BIT BIDIRECTIONAL VSSOP8; Chkd/date: USMAN/190612; Crtd /date: BAVISH/210611; Custom_Duty: 15%; Customs_HS_Code: 85423100; Distributor_name: DIGIKEY; Distributor_part_number: 296-28109-1-ND; Footprint Path: Y:\MIS_DATABASE\Library\ALTIUM_TOOL\PCB_FOOTPRINTS\Altium_Footprint_Lib.PcbLib; Height: 0.90MM; Library Path: Y:\MIS_DATABASE\Library\ALTIUM_TOOL\SCHEMATICS_PARTS\MS_MISCINTERFACE_Library.schlib; Mfr_name: TEXAS INSTRUMENTS; Mistral Part No: 141011060026-R; Package: VSSOP8; Part_type: ICS\INTERFACE; Project: SVDU; RoHS: RoHS; Temperature: -40°C+85°C; Tolerance: NA; Voltage: NA; Wattage: NA; Weight: NA; Datasheet: Y:\MIS_DATABASE\DATASHEETS\ICS\INTERFACE\TCA9406.PDF
U5 = TCA9543APWR_TSSOP14: IC 2-CHANNEL I2C BUS SWITCH WITH INTERRUPT LOGIC AND RESET TSSOP14; Chkd/date: VASANTHA/060516; Crtd /date: VASANTHA/070316; Custom_Duty: 15%; Customs_HS_Code: 85423100; Distributor_name: DIGIKEY; Distributor_part_number: 296-42157-1-ND; Footprint Path: Y:\MIS_DATABASE\Library\ALTIUM_TOOL\PCB_FOOTPRINTS\Altium_Footprint_Lib.PcbLib; Height: 1.20MM; Library Path: Y:\MIS_DATABASE\Library\ALTIUM_TOOL\SCHEMATICS_PARTS\MS_BUSDRIVERTRANSCEIVER_Library.schlib; Manufacturer: TEXAS INSTRUMENTS; Mfr_name: TEXAS INSTRUMENTS; Mistral Part No: 141016030006-R; Package: TSSOP14; Part_type: ICS\DIGITAL\BUSTRANSCEIVER; Project: OCTASIC_3600; RoHS: RoHS; Temperature: -40°C+85°C; Tolerance: NA; Voltage: NA; Wattage: NA; Weight: NA; Datasheet: Y:\MIS_DATABASE\DATASHEETS\ICS\DIGITAL\BUSTRANSCEIVER\TCA9543A.PDF
U8 = TS3DV642-Q1_WQFN42: IC 8Gbps 12-CHANNEL DIFFERENTIAL 1:2 AND 2:1 MUX WQFN42; Chkd/date: MANIRAJA/170221; Crtd /date: ALVY/170221; Custom_Duty: 15%; Customs_HS_Code: 85423100; Distributor_name: NA; Distributor_part_number: NA; Footprint Path: Y:\MIS_DATABASE\Library\ALTIUM_TOOL\PCB_FOOTPRINTS\Altium_Footprint_Lib.PcbLib; Height: 0.80MM; Library Path: Y:\MIS_DATABASE\Library\ALTIUM_TOOL\SCHEMATICS_PARTS\MS_COMBINATIONAL_Library.schlib; Mfr_name: TEXAS INSTRUMENTS; Mistral Part No: 141021020023-R; Package: WQFN42; Part_type: ICS\DIGITAL\COMBINATIONAL; Project: J7ES_SK_BRD; RoHS: RoHS; Temperature: -40°C+105°C; Tolerance: NA; Voltage: NA; Wattage: NA; Weight: NA; Datasheet: Y:\MIS_DATABASE\DATASHEETS\ICS\DIGITAL\COMBINATIONAL\TS3DV642-Q1.PDF
U50 = TLV7103318D_WSON6: IC REGULATOR LDO LINEAR 200mA WSON6; Chkd/date: NAVEED/080415; Crtd /date: JEBRAN/300315; Custom_Duty: 15%; Customs_HS_Code: 85423100; Distributor_name: DIGIKEY; Distributor_part_number: 296-29058-1-ND; Height: 0.80MM; Manufacturer: TEXAS INSTRUMENTS; Mfr_name: TEXAS INSTRUMENTS; Mistral Part No: 142015030017-R; Package: WSON6; Part_type: ICS\POWER\VOLTAGE REGULATOR; Project: DUET BOARDS; RoHS: RoHS; Temperature: -40°C+125°C; Tolerance: NA; Voltage: NA; Wattage: NA; Weight: NA; Datasheet: Y:\MIS_DATABASE\DATASHEETS\MISC\REGULATORS\TLV71-SER.PDF

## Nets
DGND: C4.2 C5.1 C7.2 C8.2 C10.1 C11.1 C13.1 C112.1 C168.2 C169.2 C170.2 C171.2 C175.2 C176.1 C178.1 C180.1 C187.2 C188.1 C440.2 C441.1 D5.2(ANODE) D6.1(GND) D11.2(ANODE) J1.12 J1.16 J1.24 J1.SH1 J1.SH2 J1.SH3 J1.SH4 J15.A1(GND) J15.A12(GND) J15.B1(GND) J15.B12(GND) J20.1 J20.4 J20.7 J20.10 J20.13 J20.16 J20.19 J20.SH1 J20.SH2 LD3.1(CATHODE) LD6.1(CATHODE) Q1.4(S1) Q1.7(S2) Q4.4(S1) Q4.7(S2) Q8.2(EMITTER) R5.1 R15.2 R21.1 R164.1 R177.1 R193.2 R245.2 R251.2 R255.2 R283.1 R324.1 R328.1 U3.2(GND) U4.11(GND) U4.21(PAD) U5.7(GND) U8.43(EP) U40.3(GND) U50.4(GND) U54.10(GND1) U54.11(GND2) U95.8(GND) U104.1(GND) U104.2(GND) U104.3(GND) U104.7(GND) ; also on sheet 9 10 11 12 13 14 15 16 17 18 19 20 21 22 23 24 25 26 27 28 29 30 31 32 33 34 38 39 40 41 42 43
VBUS_TYPEC2: J15.A4(VBUS1) J15.A9(VBUS2) J15.B4(VBUS3) J15.B9(VBUS4) R203.1 U104.4(IN1) U104.5(IN2) U104.6(IN3) ; also on sheet 9 34
VCC1V8_SYS: C178.2 U54.2(VCCB) ; also on sheet 12 13 17 18 20 33 38 39 41
VCC3V3_EXP: R293.1 R294.1 ; also on sheet 32
VCC_3V3_SYS: C4.1 C5.2 C7.1 C13.2 C112.2 C169.1 C170.1 C176.2 C180.2 C187.1 C188.2 C441.2 J1.30 J1.32 J1.34 J1.36 J20.22 R16.1 R17.1 R29.1 R30.1 R31.1 R32.1 R38.1 R39.1 R62.2 R143.2 R150.2 R162.2 R179.2 R263.2 R278.1 R279.1 R285.2 R292.1 U3.7(VCCB) U4.19(VCCB) U5.14(VCC) U8.1(VCC) U40.5(VCC) U54.3(VCCA) U95.16(VCC) ; also on sheet 9 10 12 13 17 18 19 21 22 23 25 26 28 29 30 32 33 34 38 39 40 41 42
VCC_5V0: C171.1 C175.1 U50.2(IN) U50.3(EN2) ; also on sheet 9 10 23 32 34 40
VCC_CSI_IO: C8.1 C10.2 C11.2 C168.1 J1.38 J1.40 R4.2 R20.2 R245.1 R246.1 R247.2 R248.2 R249.1 U3.3(VCCA) U4.2(VCCA)
VDDR_CORE: R384.1 ; also on sheet 13 14 15
CSI0_FLEX_RXCLKN: J20.8 U8.28(D0-B)
CSI0_FLEX_RXCLKP: J20.9 U8.29(D0+B)
CSI0_FLEX_RXN0: J20.2 U8.26(D1-B)
CSI0_FLEX_RXN1: J20.5 U8.24(D2-B)
CSI0_FLEX_RXN2: J20.11 U8.22(D3-B)
CSI0_FLEX_RXN3: J20.14 U8.20(CEC_B)
CSI0_FLEX_RXP0: J20.3 U8.27(D1+B)
CSI0_FLEX_RXP1: J20.6 U8.25(D2+B)
CSI0_FLEX_RXP2: J20.12 U8.23(D3+B)
CSI0_FLEX_RXP3: J20.15 U8.21(HPD_B)
CSI0_MIPI_RXCLKN: J1.7 U8.37(D0-A)
CSI0_MIPI_RXCLKP: J1.5 U8.38(D0+A)
CSI0_MIPI_RXN0: J1.11 U8.35(D1-A)
CSI0_MIPI_RXN1: J1.15 U8.33(D2-A)
CSI0_MIPI_RXN2: J1.19 U8.31(D3-A)
CSI0_MIPI_RXN3: J1.23 U8.18(CEC_A)
CSI0_MIPI_RXP0: J1.9 U8.36(D1+A)
CSI0_MIPI_RXP1: J1.13 U8.34(D2+A)
CSI0_MIPI_RXP2: J1.17 U8.32(D3+A)
CSI0_MIPI_RXP3: J1.21 U8.19(HPD_A)
CSI0_RXCLKN: U8.6(D0-) U18.AB14(CSI0_RXCLKN)
CSI0_RXCLKP: U8.5(D0+) U18.AB13(CSI0_RXCLKP)
CSI0_RXN0: U8.8(D1-) U18.W12(CSI0_RXN0)
CSI0_RXN1: U8.11(D2-) U18.Y13(CSI0_RXN1)
CSI0_RXN2: U8.13(D3-) U18.AA13(CSI0_RXN2)
CSI0_RXN3: U8.15(CEC) U18.AB11(CSI0_RXN3)
CSI0_RXP0: U8.7(D1+) U18.W13(CSI0_RXP0)
CSI0_RXP1: U8.10(D2+) U18.Y14(CSI0_RXP1)
CSI0_RXP2: U8.12(D3+) U18.AA12(CSI0_RXP2)
CSI0_RXP3: U8.14(HPD) U18.AB10(CSI0_RXP3)
CSI0_RXRCALIB: R328.2 U18.V10(CSI0_RXRCALIB)
CSI_EN: R292.2 U8.2(EN) ; also on sheet 39
CSI_GPIO0: J20.17 U4.20(B1) ; also on sheet 39
CSI_GPIO1: J20.18 U4.18(B2) ; also on sheet 39
CSI_GPIO2: U4.17(B3) ; also on sheet 41
CSI_GPIO3: U4.16(B4) ; also on sheet 41
CSI_GPIO4: U4.15(B5) ; also on sheet 41
CSI_I2C2_nINT1: R29.2 U5.8(~{INT1})
CSI_I2C2_SCL: J20.20 R31.2 U3.8(SCL_B) U5.10(SC1)
CSI_I2C2_SDA: J20.21 R30.2 U3.1(SDA_B) U5.9(SD1)
CSI_I2C_LT_EN: R4.1 R5.2 U3.6(OE)
CSI_MIPI_GPIO0: J1.6 U4.1(A1)
CSI_MIPI_GPIO1: J1.8 U4.3(A2)
CSI_MIPI_GPIO2: J1.18 U4.4(A3)
CSI_MIPI_GPIO3: J1.20 U4.5(A4)
CSI_MIPI_GPIO4: J1.22 U4.6(A5)
CSI_MIPI_I2C2_SCL: J1.2 R246.2 U3.5(SCL_A)
CSI_MIPI_I2C2_SDA: J1.4 R249.2 U3.4(SDA_A)
CSI_MIPI_LT_EN: R20.1 R21.2 U4.10(OE)
CSI_MIPI_RSTz: J1.14 R255.1 U4.7(A6)
CSI_REFCLK: J1.10 TP1.1(TP) ; also on sheet 24
CSI_RSTz: U4.14(B6) ; also on sheet 39
CSI_SEL1: R39.2 U8.16(SEL1)
CSI_SEL2: R38.2 U8.17(SEL2) ; also on sheet 39
CSI_VLDO_SEL: R251.1 U50.1(EN1) ; also on sheet 39
EXP_I2C2_nINT0: R17.2 U5.4(~{INT0})
EXP_I2C2_SCL: R293.2 U5.6(SC0) ; also on sheet 32
EXP_I2C2_SDA: R294.2 U5.5(SD0) ; also on sheet 32
EXP_SPI2_CLK: U95.5(2B1) ; also on sheet 32
EXP_SPI2_CS0/EHRPWM0_A: U95.2(1B1) ; also on sheet 32
EXP_SPI2_D0: U95.11(3B1) ; also on sheet 32
EXP_SPI2_D1/ECAP2_IN_APWM_OUT: U95.14(4B1) ; also on sheet 32
IO_EXP_TEST_LED: R163.1 R164.2 ; also on sheet 39
RESETSTATz: U5.3(~{RESET}) ; also on sheet 18 19 20 22 23 26 38 39 40 41
SOC_GPIO1_49: R323.1 R324.2 ; also on sheet 18
SoC_I2C2_SCL: R279.2 U5.12(SCL) ; also on sheet 31
SoC_I2C2_SDA: R278.2 U5.13(SDA) ; also on sheet 31
SOC_SPI2_CLK: U54.8(2A1) U95.7(2A) ; also on sheet 32
SOC_SPI2_CS0: U54.6(1A1) U95.4(1A) ; also on sheet 32
SOC_SPI2_D0: U54.7(1A2) U95.9(3A) ; also on sheet 32
SOC_SPI2_D1: U54.9(2A2) U95.12(4A) ; also on sheet 32
SOC_UART1_CTS: U95.10(3B2) ; also on sheet 30
SOC_UART1_CTS_BT: U54.14(1B2) ; also on sheet 17
SOC_UART1_RTS: U95.13(4B2) ; also on sheet 30
SOC_UART1_RTS_BT: U54.12(2B2) ; also on sheet 17
SOC_UART1_RX_BT: U54.15(1B1) ; also on sheet 17
SOC_UART1_RXD: U95.3(1B2) ; also on sheet 30
SOC_UART1_TX_BT: U54.13(2B1) ; also on sheet 17
SOC_UART1_TXD: U95.6(2B2) ; also on sheet 30
SoC_USB0_DM: L7.4(OUT2) ; also on sheet 34
SoC_USB0_DP: L7.1(IN1) ; also on sheet 34
UART1_FET_BUF_EN: R263.1 U40.2(A) U54.1(~{1OE}) U54.16(~{2OE}) ; also on sheet 39
UART1_FET_BUF_EN_INV: U40.4(Y) U95.15(~{OE})
UART1_FET_SEL: R177.2 R179.1 U95.1(S) ; also on sheet 39
USB_TYPEC2_EARTH: C440.1 J15.SH1 J15.SH2 J15.SH3 J15.SH4 R193.1
USBC_CONN2_CC1: D5.1(CATHODE) J15.A5(CC1) ; also on sheet 9
USBC_CONN2_CC2: D11.1(CATHODE) J15.B5(CC2) ; also on sheet 9
USBC_CONN2_DM: D6.3(IO2) J15.A7(D-_1) J15.B7(D-_2) L7.3(OUT1)
USBC_CONN2_DP: D6.2(IO1) J15.A6(D+_1) J15.B6(D+_2) L7.2(IN2)
VLDO_CSI_1V8: R248.1 U50.5(OUT2)
VLDO_CSI_3V3: R247.1 U50.6(OUT1)
N17031262: LD6.2(ANODE) R203.2
N20878915: R16.2 U5.1(A0)
N20878927: R15.1 U5.2(A1)
N20878931: R32.2 U5.11(~{INT})
N20933818: R283.2 U54.4(1DIR)
N20933822: R285.1 U54.5(2DIR)
N22685157: LD2.1(CATHODE) Q8.3(COLLECTOR)
N22685161: LD2.2(ANODE) R143.1
N22685196: Q8.1(BASE) R384.2
N22685214: LD3.2(ANODE) R150.1
N22685527: LD5.1(CATHODE) Q1.1(D1) Q1.2(D2) Q1.5(D3) Q1.6(D4) Q1.8(D5)
N22685551: LD1.1(CATHODE) Q4.1(D1) Q4.2(D2) Q4.5(D3) Q4.6(D4) Q4.8(D5)
N22685595: Q4.3(G) R323.2
N22685622: LD1.2(ANODE) R62.1
N22685670: Q1.3(G) R163.2
N22685686: LD5.2(ANODE) R162.1

Not connected (* = marked no-connect by the designer): J1 1* 3* 25* 26* 27* 28* 29* 31* 33* 35* 37* 39*; J15 A2(TX1+)* A3(TX1-)* A8(SBU1)* A10(RX2-)* A11(RX2+)* B2(TX2+)* B3(TX2-)* B8(SBU2)* B10(RX1-)* B11(RX1+)*; U4 8(A7)* 9(A8)* 12(B8)* 13(B7)*; U8 3(SCL)* 4(SDA)* 9(NC1) 30(NC2) 39(SDA_B)* 40(SCL_B)* 41(SDA_A)* 42(SCL_A)*; U18 U11(RSVD6)* V11(RSVD7)*; U40 1(NC)*

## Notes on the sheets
sheet 35
- USB0 TYPE-C DRP
- Silk: TYPE-C DRP
- 90E
- DLW21SZ900HQ2B
- POWER INDICATION LED: VBUS_TYPEC2
- USER TEST LEDS
- POWER RAIL LEDS
- SoC GPIO
- IO EXP GPIO
- VBE = 0.85V
  Ic = 20mA
  Ib = 0.2mA
sheet 36
- SoC UART1 FET SWITCH & BUFFER
- OEn
- SEL
- INPUT/OUTPUT
- An
- L
- L
- An=nB1
- SOC - EXP CONN
- L
- H(DEFAULT)
- An=nB2
- SOC - FT4232
- SoC_MAIN_UART1_RXD
- SoC_MAIN_UART1_CTS
- SoC_MAIN_UART1_TXD
- SoC_MAIN_UART1_RTS
- 2DIR=H : 2A ->2B
  1DIR=L : 1B ->1A
- (VCCA < OR = VCCB)
sheet 37
- CSI INTERFACE
- Reserved Pins
- Silk: CSI
- CSI - 1:2  MUX : Truth Table
- MUX_SEL_2
- FUNCTION
- LOW
- INPUT<--A port [CSI2 Connector]
- HIGH
- INPUT<--B port [Flex Camera Connector]
- (default)
- [SCL]
- [SDA]
- I2C SWITCH FOR SoC_I2C2
- [GPIO/PWM_A]
- [GPIO/PWM_B]
- [25MHz_REFCLK]
- [RESETz]
- [MOSI/GPIO]
- [SCLK/GPO]
- [CS/GPIO]
- [3V3]
- [VIO]
- I2C ADDRESS: 0x71
- MIPI SIDE
- SOC SIDE
- (VCCA < or = VCCB)
- CSI_VLDO_SEL
- LDO VTG
- LOW
- 1.8V (Default)
- Note: 1K res is to bleed off the voltage.
- High
- 3.3V
- Controlled through IO Expander.
